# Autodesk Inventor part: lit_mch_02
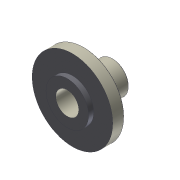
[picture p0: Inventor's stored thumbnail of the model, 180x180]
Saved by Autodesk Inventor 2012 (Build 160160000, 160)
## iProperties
Created: 2002-07
Part Number: lit_mch_02
Document SubType Name: Modeling
Designer: Lieven Grauls
Stock Number: lit_mch_02
Project: Valve Techcamp 2008
Density: 1 g/cm^3
Mass: 297.985 g
Surface Area: 511.854 cm^2
Volume: 297.985 cm^3
Material: Default
Company: Autodesk
Control State: 0
Master: False
Checked Out: False
Shininess: 64.0
Length Units: 11269
Angle Units: 11279
Time Units: 11290
Mass Units: 11283
Length Display Precision: 3
Angle Display Precision: 2
Density: 0.0
Volumn: 0.0
Area: 0.0
PropertySet Name: Model Information
Author: Lieven Grauls
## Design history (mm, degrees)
node "lit_cast_02" dims "d1" = 10
sketch "Sketch2"
  geometry: L1 (0, 35.8)-(0, -11.8) reference; L2 (0, 1)-(37, 1); L3 (20, 1)-(-20, 1) reference; L4 (37, 1)-(37, 10); L5 (37, 10)-(75, 10); L6 (75, 10)-(75, -5); L7 (75, -5)-(0, -5); L8 (70, 29)-(70, 10) reference; L9 (69, 9)-(-69, 9) reference; L10 (37, 0)-(-37, 0) reference; 1 further point
  constraints: 10 end point, 2 parallel, 2 perpendicular, 2 point on line, 1 collinear
  dimensions: "d2" = 1 distance between parallel lines of L10 L2; "d3" = 1 distance between parallel lines of L9 L5; "d4" = 5 distance between parallel lines of L6 L8; "d5" = 5 distance between parallel lines of L7 L10; "d6" = 74 diameter of L4 L1
revolve "Revolution1" sketch "Sketch2" stored, may be unused: angle "d7" = 90 deg
sketch "Sketch8"
  geometry: C1 r 6.335 at (0.483, 0); C2 r 27 at (0, 0) reference; 1 further point
  constraints: 1 centre point
  dimensions: "d63" = 12.67 diameter of C1
extrude "Extrusion2" join sketch "Sketch8" stored distance "d61" = 10; taper "d62" = 0 deg
extrude "Extrusion3" cut sketch "Sketch8" stored distance "d64" = 10; taper "d65" = 0 deg
node "Volumenkörper1"
node "Volumenkörpern"
node "Oberflächenkörpern"
tag "Bezeichnung2"
feature "Volumenkörper1::lit_cast_02" dims "d1" = 10
